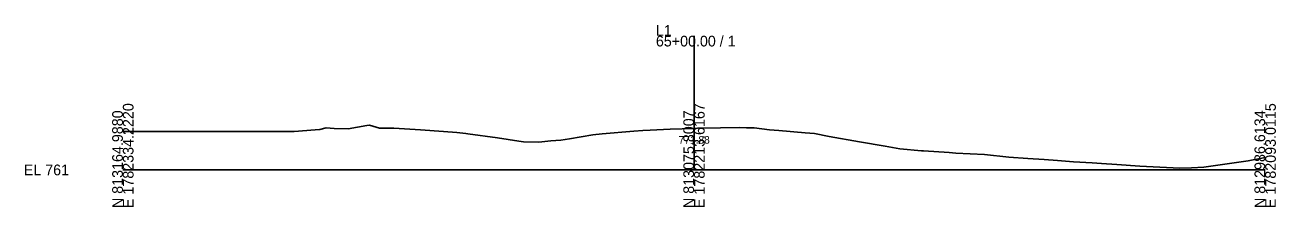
# Model space of a CAD drawing. Extents: x 5574 to 10203, y -10 to 9546.
# Drawn here: x 7574.3 to 7902.8, y 2490.3 to 2538 of the extents above; entities that cross this region are included whole.
import ezdxf

# ---------------------------------------------------------------- set-up
doc = ezdxf.new("R2010")
doc.units = 0
for name, color, linetype in [('Exist Cross Section Cell', 7, 'Continuous'), ('Exist XS Center Line Elevation Label', 7, 'Continuous'), ('Exist XS Ground Line', 7, 'Continuous')]:
    doc.layers.add(name, color=color, linetype=linetype)

msp = doc.modelspace()

# ---------------------------------------------------------------- linework, layer by layer
at = {"layer": 'Exist Cross Section Cell'}
for p, q in [((7750, 2500), (7750, 2535.15)), ((7600, 2500), (7750, 2500)), ((7750, 2500), (7900, 2500))]:
    msp.add_line(p, q, dxfattribs=at)
at = {"layer": 'Exist XS Ground Line'}
for p, q in [((7600, 2510.03), (7611.04, 2510.03)), ((7611.04, 2510.03), (7615.37, 2510.03)), ((7615.37, 2510.03), (7619.28, 2510.03)), ((7619.28, 2510.03), (7628.41, 2510.03)), ((7628.41, 2510.03), (7632.49, 2510.03)), ((7632.49, 2510.03), (7642.11, 2510.03)), ((7642.11, 2510.03), (7644.14, 2510.03)), ((7644.14, 2510.03), (7644.99, 2510.03)), ((7644.99, 2510.03), (7650.49, 2510.48)), ((7650.49, 2510.48), (7651.73, 2510.6)), ((7651.73, 2510.6), (7653.43, 2511.04)), ((7653.43, 2511.04), (7655.52, 2510.84)), ((7655.52, 2510.84), (7659.2, 2510.76)), ((7659.2, 2510.76), (7664.04, 2511.64)), ((7664.04, 2511.64), (7664.74, 2511.72)), ((7664.74, 2511.72), (7667.4, 2510.91)), ((7667.4, 2510.91), (7671.16, 2510.96)), ((7671.16, 2510.96), (7678.19, 2510.51)), ((7678.19, 2510.51), (7684.17, 2510.07)), ((7684.17, 2510.07), (7687.71, 2509.79)), ((7725.92, 2509.46), (7734.24, 2510.18)), ((7734.24, 2510.18), (7736.56, 2510.34)), ((7736.56, 2510.34), (7738.45, 2510.46)), ((7738.45, 2510.46), (7743.72, 2510.65)), ((7743.72, 2510.65), (7750, 2510.88)), ((7750, 2510.88), (7750.9, 2510.91)), ((7750.9, 2510.91), (7756.95, 2511.04)), ((7756.95, 2511.04), (7762, 2511.15)), ((7762, 2511.15), (7763.77, 2511.07)), ((7763.77, 2511.07), (7765.78, 2510.99)), ((7765.78, 2510.99), (7769.8, 2510.54)), ((7769.8, 2510.54), (7772.28, 2510.32)), ((7772.28, 2510.32), (7779.17, 2509.76)), ((7687.71, 2509.79), (7690.05, 2509.56)), ((7690.05, 2509.56), (7690.62, 2509.47)), ((7690.62, 2509.47), (7698.43, 2508.44)), ((7698.43, 2508.44), (7703.98, 2507.58)), ((7703.98, 2507.58), (7705.25, 2507.4)), ((7705.25, 2507.4), (7709.27, 2507.3)), ((7709.27, 2507.3), (7712.39, 2507.59)), ((7712.39, 2507.59), (7714.99, 2507.8)), ((7714.99, 2507.8), (7717.29, 2508.18)), ((7717.29, 2508.18), (7723.44, 2509.23)), ((7723.44, 2509.23), (7725.92, 2509.46)), ((7779.17, 2509.76), (7781.67, 2509.51)), ((7781.67, 2509.51), (7785.47, 2508.79)), ((7785.47, 2508.79), (7793.49, 2507.36)), ((7793.49, 2507.36), (7800.2, 2506.2)), ((7800.2, 2506.2), (7804.07, 2505.53)), ((7804.07, 2505.53), (7809.78, 2505.04)), ((7809.78, 2505.04), (7810.28, 2505)), ((7810.28, 2505), (7817.04, 2504.53)), ((7817.04, 2504.53), (7818.78, 2504.42)), ((7818.78, 2504.42), (7826.28, 2504.05)), ((7826.28, 2504.05), (7832.67, 2503.32)), ((7832.67, 2503.32), (7837.65, 2503.02)), ((7837.65, 2503.02), (7841.99, 2502.71)), ((7841.99, 2502.71), (7845.47, 2502.45)), ((7845.47, 2502.45), (7849.62, 2502.14)), ((7849.62, 2502.14), (7854.53, 2501.9)), ((7854.53, 2501.9), (7857.05, 2501.67)), ((7857.05, 2501.67), (7861.03, 2501.4)), ((7861.03, 2501.4), (7867.07, 2500.98)), ((7867.07, 2500.98), (7870.61, 2500.81)), ((7870.61, 2500.81), (7877.61, 2500.5)), ((7877.61, 2500.5), (7880.68, 2500.59)), ((7880.68, 2500.59), (7883.91, 2500.73)), ((7883.91, 2500.73), (7887.59, 2501.26)), ((7887.59, 2501.26), (7895.57, 2502.42)), ((7895.57, 2502.42), (7900, 2503.29))]:
    msp.add_line(p, q, dxfattribs=at)

# ---------------------------------------------------------------- texts
at = {"layer": 'Exist Cross Section Cell'}
for s, p in [('L1', (7740, 2535.15)), ('65+00.00 / 1', (7740, 2532.35)), ('EL 761', (7574, 2498.6))]:
    msp.add_text(s, height=2.8, dxfattribs=at).set_placement(p)
for s, p in [('E 1782334.2220', (7602.8, 2490)), ('E 1782213.6167', (7752.8, 2490)), ('E 1782093.0115', (7902.8, 2490)), ('N 813164.9880', (7600, 2490)), ('N 813075.8007', (7750, 2490)), ('N 812986.6134', (7900, 2490))]:
    msp.add_text(s, height=2.8, rotation=90, dxfattribs=at).set_placement(p)
at = {"layer": 'Exist XS Center Line Elevation Label'}
msp.add_text('771.88', height=2, dxfattribs=at).set_placement((7745.96, 2506.88))

doc.saveas('drawing.dxf')
